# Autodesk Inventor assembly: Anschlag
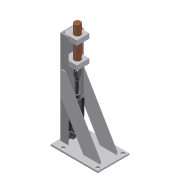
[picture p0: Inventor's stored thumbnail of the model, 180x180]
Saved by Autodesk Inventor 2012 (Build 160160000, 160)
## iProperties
Company: CAD-Verlag
Created: 2004-09
Part Number: Anschlag
Document SubType Name: Assembly
Designer: Greiling
Manufacturer: Standard
Standards Organization: Custom
Checked By: Jürgen Kronas
Stock Number: 10-10007
Author: Juergen Kronas
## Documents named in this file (11)
- C:\DemoDaten2012\CAD Daten\Daten Vault 2012 Inventor\Kapitel 4\Anschlag\Anschlag.iam
- C:\DemoDaten2012\CAD Daten\Daten Vault 2012 Inventor\Kapitel 4\Anschlag\Ständer.iam
- C:\DemoDaten2012\CAD Daten\Daten Vault 2012 Inventor\Kapitel 4\Anschlag\local.DIN.37.480.8.ipt
- C:\DemoDaten2012\CAD Daten\Daten Vault 2012 Inventor\Kapitel 4\Anschlag\Bolzenführung.iam
- C:\DemoDaten2012\CAD Daten\Daten Vault 2012 Inventor\Kapitel 4\Anschlag\Anschlag_Rund.ipt
- C:\DemoDaten2012\CAD Daten\Daten Vault 2012 Inventor\Kapitel 4\Anschlag\532740_DNCB_40_80_PPV_A_1.iam
- C:\DemoDaten2012\CAD Daten\Daten Vault 2012 Inventor\Kapitel 4\Anschlag\LNG_40.ipt
- C:\DemoDaten2012\CAD Daten\Daten Vault 2012 Inventor\Kapitel 4\Anschlag\SG_M12.ipt
- C:\DemoDaten2012\CAD Daten\Daten Vault 2012 Inventor\Kapitel 4\Anschlag\SNCB_40.ipt
- C:\DemoDaten2012\CAD Daten\Daten Vault 2012 Inventor\Kapitel 4\Anschlag\local.DIN.179.11.8.ipt
- C:\DemoDaten2012\CAD Daten\Daten Vault 2012 Inventor\Kapitel 4\Anschlag\local.DIN.19.192.8.ipt
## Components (20 placed, 10 different names)
1. Ständer:1 [sub-assembly] — Passend:1, Passend:2, Passend:3, Passend:4, Passend:5, Passend:8, Passend:9, Passend:10, Passend:15, Passend:17, Passend:20, Passend:21, Einfügen:2, Einfügen:3, Einfügen:5
2. Bolzenführung:1 [sub-assembly] — Passend:4, Passend:5, Passend:6
3. Bolzenführung:2 [sub-assembly] — Passend:1, Passend:2, Passend:3, Passend:6, Passend:7
4. Anschlag_Rund:1 — Passend:7, Passend:15, Passend:16
5. 532740_DNCB_40_80_PPV_A_1:1 [sub-assembly] — Passend:11, Passend:12, Passend:13, Passend:18, Passend:19
6. LNG_40:1 — Passend:11, Passend:12, Passend:13, Passend:14
7. SG_M12:1 — Passend:16, Passend:17, Passend:18, Passend:19
8. SNCB_40:1 — Passend:8, Passend:9, Passend:10, Passend:14, Einfügen:4
9. DIN 912  (Regelgewinde) - ersetzt durch DIN EN ISO 4762 M4 x 10:1 — Einfügen:2
10. DIN 912  (Regelgewinde) - ersetzt durch DIN EN ISO 4762 M4 x 10:2 — Einfügen:3
11. DIN 912  (Regelgewinde) - ersetzt durch DIN EN ISO 4762 M4 x 10:3 — Einfügen:4
12. DIN 912  (Regelgewinde) - ersetzt durch DIN EN ISO 4762 M4 x 10:4 — Einfügen:5
13. DIN 127 - zurückgezogen A 10:1 — Passend:20, Passend:21, Einfügen:1
14. DIN 933  (Regelgewinde) - ersetzt durch DIN EN 24 017 M10  x 25:1 — Einfügen:1
15. DIN 127 - zurückgezogen A 10:2
16. DIN 933  (Regelgewinde) - ersetzt durch DIN EN 24 017 M10  x 25:2
17. DIN 127 - zurückgezogen A 10:3
18. DIN 933  (Regelgewinde) - ersetzt durch DIN EN 24 017 M10  x 25:3
19. DIN 127 - zurückgezogen A 10:4
20. DIN 933  (Regelgewinde) - ersetzt durch DIN EN 24 017 M10  x 25:4
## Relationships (26: Mate 21, Insert 5)
- Passend:1 [Mate]: Ständer:1 ↔ Bolzenführung:2
- Passend:2 [Mate]: Ständer:1 ↔ Bolzenführung:2
- Passend:3 [Mate]: Ständer:1 ↔ Bolzenführung:2
- Passend:4 [Mate]: Ständer:1 ↔ Bolzenführung:1
- Passend:5 [Mate]: Ständer:1 ↔ Bolzenführung:1
- Passend:6 [Mate]: Bolzenführung:1 ↔ Bolzenführung:2
- Passend:7 [Mate]: Bolzenführung:2 ↔ Anschlag_Rund:1
- Passend:8 [Mate]: Ständer:1 ↔ SNCB_40:1
- Passend:9 [Mate]: Ständer:1 ↔ SNCB_40:1
- Passend:10 [Mate]: Ständer:1 ↔ SNCB_40:1
- Passend:11 [Mate]: 532740_DNCB_40_80_PPV_A_1:1 ↔ LNG_40:1
- Passend:12 [Mate]: 532740_DNCB_40_80_PPV_A_1:1 ↔ LNG_40:1
- Passend:13 [Mate]: 532740_DNCB_40_80_PPV_A_1:1 ↔ LNG_40:1
- Passend:14 [Mate]: LNG_40:1 ↔ SNCB_40:1
- Passend:15 [Mate]: Ständer:1 ↔ Anschlag_Rund:1
- Passend:16 [Mate]: Anschlag_Rund:1 ↔ SG_M12:1
- Passend:17 [Mate]: Ständer:1 ↔ SG_M12:1
- Passend:18 [Mate]: 532740_DNCB_40_80_PPV_A_1:1 ↔ SG_M12:1
- Passend:19 [Mate]: 532740_DNCB_40_80_PPV_A_1:1 ↔ SG_M12:1
- Passend:20 [Mate]: Ständer:1 ↔ DIN 127 - zurückgezogen A 10:1
- Passend:21 [Mate]: Ständer:1 ↔ DIN 127 - zurückgezogen A 10:1
- Einfügen:1 [Insert]: DIN 127 - zurückgezogen A 10:1 ↔ DIN 933  (Regelgewinde) - ersetzt durch DIN EN 24 017 M10  x 25:1
- Einfügen:2 [Insert]: Ständer:1 ↔ DIN 912  (Regelgewinde) - ersetzt durch DIN EN ISO 4762 M4 x 10:1
- Einfügen:3 [Insert]: Ständer:1 ↔ DIN 912  (Regelgewinde) - ersetzt durch DIN EN ISO 4762 M4 x 10:2
- Einfügen:5 [Insert]: Ständer:1 ↔ DIN 912  (Regelgewinde) - ersetzt durch DIN EN ISO 4762 M4 x 10:4
- Einfügen:4 [Insert]: SNCB_40:1 ↔ DIN 912  (Regelgewinde) - ersetzt durch DIN EN ISO 4762 M4 x 10:3
